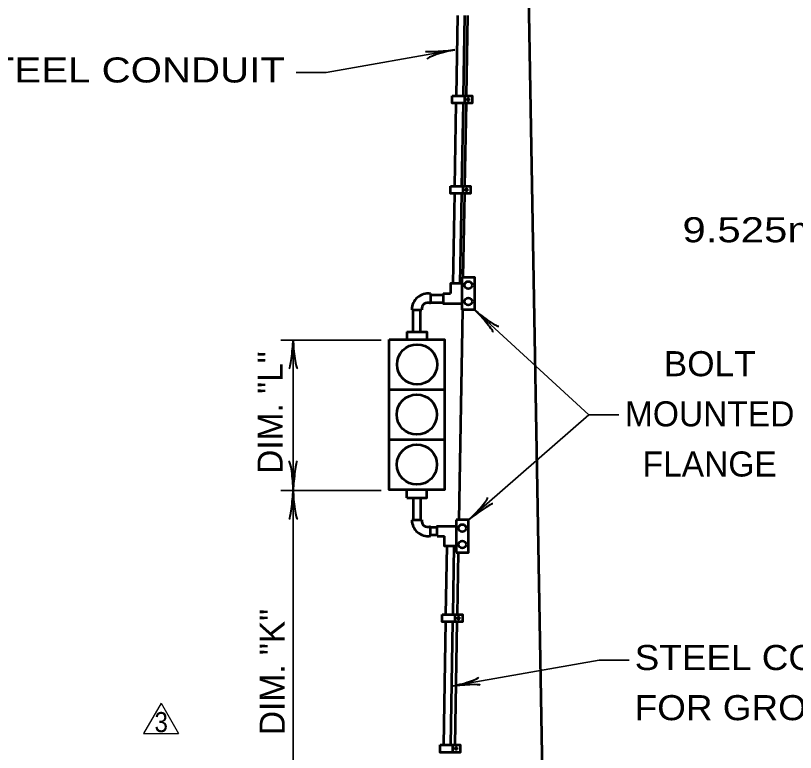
# Model space of a CAD drawing. Extents: x 14808 to 15663, y 10944 to 11488.
# Drawn here: x 15128.3 to 15221.6, y 11289.8 to 11377.9 of the extents above; entities that cross this region are included whole.
import ezdxf
from ezdxf.enums import TextEntityAlignment as Align

# ---------------------------------------------------------------- set-up
doc = ezdxf.new("R2010")
doc.units = 0
doc.header["$LTSCALE"] = 1.2
doc.layers.add('1', color=7, linetype='Continuous', lineweight=53)

msp = doc.modelspace()

# ---------------------------------------------------------------- linework, layer by layer
at = {"layer": '1'}
for p, q in [((15188.438, 11450.597), (15191.474, 11276.623)), ((15181.167, 11377.907), (15181, 11368.32)), ((15182.007, 11377.912), (15181.84, 11368.318)), ((15182.369, 11377.912), (15182.202, 11368.318)), ((15182.016, 11368.319), (15182.016, 11367.419)), ((15180.984, 11367.414), (15180.811, 11357.513)), ((15181.824, 11367.414), (15181.651, 11357.521)), ((15182.186, 11367.416), (15182.013, 11357.517)), ((15181.815, 11357.515), (15181.815, 11356.615)), ((15180.795, 11356.616), (15180.608, 11345.87)), ((15181.635, 11356.611), (15181.448, 11345.87)), ((15181.997, 11356.607), (15181.823, 11346.623)), ((15181.704, 11342.722), (15181.704, 11346.623)), ((15177.933, 11344.67), (15177.933, 11343.47)), ((15177.933, 11344.496), (15179.397, 11344.496)), ((15179.433, 11344.67), (15180.333, 11344.67)), ((15177.933, 11343.603), (15179.416, 11343.603)), ((15175.704, 11342.722), (15176.904, 11342.722)), ((15175.862, 11340.065), (15175.862, 11342.729)), ((15176.755, 11340.065), (15176.755, 11342.748)), ((15181.755, 11342.722), (15181.316, 11317.584)), ((15175.109, 11340.065), (15175.109, 11339.165)), ((15173.009, 11333.165), (15179.609, 11333.165)), ((15179.609, 11327.165), (15173.009, 11327.165)), ((15175.109, 11320.228), (15175.109, 11321.128)), ((15175.862, 11320.228), (15175.862, 11317.564)), ((15176.755, 11320.228), (15176.755, 11317.545)), ((15175.704, 11317.571), (15176.904, 11317.571)), ((15180.99, 11317.589), (15180.99, 11313.689)), ((15182.49, 11317.589), (15180.99, 11317.589)), ((15177.933, 11315.673), (15177.933, 11316.823)), ((15177.933, 11316.689), (15178.719, 11316.689)), ((15177.933, 11315.796), (15178.719, 11315.796)), ((15178.719, 11315.641), (15179.619, 11315.641)), ((15179.89, 11314.45), (15179.747, 11306.274)), ((15180.73, 11314.45), (15180.587, 11306.274)), ((15181.248, 11313.675), (15181.119, 11306.274)), ((15180.846, 11306.274), (15180.846, 11305.374)), ((15179.731, 11305.364), (15179.474, 11290.658)), ((15180.571, 11305.364), (15180.314, 11290.658)), ((15181.103, 11305.364), (15180.846, 11290.667)), ((15180.577, 11290.659), (15180.577, 11289.759))]:
    msp.add_line(p, q, dxfattribs=at)
at = {"layer": '1', "lineweight": 35}
for p, q in [((15183.204, 11342.722), (15196.87, 11330.165)), ((15172.04, 11339.093), (15160.04, 11339.093)), ((15172.04, 11321.093), (15160.04, 11321.093))]:
    msp.add_line(p, q, dxfattribs=at)
at = {"layer": '1', "lineweight": 25}
for p, q in [((15145.704, 11295.641), (15143.604, 11292.003)), ((15145.704, 11295.641), (15147.804, 11292.003)), ((15143.604, 11292.003), (15147.804, 11292.003))]:
    msp.add_line(p, q, dxfattribs=at)
at = {"layer": '1', "lineweight": 35}
for points in [[(15180.826, 11373.816), (15165.463, 11371.107), (15161.863, 11371.107)], [(15161.508, 11339.136), (15161.508, 11321.136), (15161.508, 11276.623)], [(15182.49, 11317.589), (15196.87, 11330.165), (15200.47, 11330.165)], [(15180.393, 11297.665), (15198.119, 11300.79), (15201.719, 11300.79)]]:
    msp.add_lwpolyline(points, dxfattribs=at)
at = {"layer": '1'}
for points in [[(15180.516, 11368.319), (15182.916, 11368.319), (15182.916, 11367.419), (15180.516, 11367.419)], [(15180.315, 11357.515), (15182.715, 11357.515), (15182.715, 11356.615), (15180.315, 11356.615)], [(15173.009, 11339.165), (15179.609, 11339.165), (15179.609, 11321.165), (15173.009, 11321.165)], [(15179.346, 11306.274), (15181.746, 11306.274), (15181.746, 11305.374), (15179.346, 11305.374)], [(15179.077, 11290.659), (15181.477, 11290.659), (15181.477, 11289.759), (15179.077, 11289.759)]]:
    msp.add_lwpolyline(points, close=True, dxfattribs=at)
for points in [[(15181.704, 11346.623), (15183.204, 11346.623), (15183.204, 11342.722)], [(15181.699, 11345.87), (15180.333, 11345.87), (15180.333, 11344.67)], [(15179.433, 11344.67), (15179.433, 11343.47), (15181.695, 11343.47)], [(15183.204, 11342.722), (15181.802, 11342.722), (15181.704, 11342.722)], [(15175.109, 11340.065), (15177.509, 11340.065), (15177.509, 11339.165)], [(15175.109, 11320.228), (15177.509, 11320.228), (15177.509, 11321.128)], [(15180.99, 11313.689), (15182.49, 11313.689), (15182.49, 11317.589)], [(15178.719, 11315.641), (15178.719, 11316.841), (15180.981, 11316.841)], [(15180.985, 11314.441), (15179.619, 11314.441), (15179.619, 11315.641)]]:
    msp.add_lwpolyline(points, dxfattribs=at)
for centre, radius in [((15182.453, 11367.873), 0.12), ((15182.252, 11357.069), 0.12), ((15182.457, 11345.674), 0.444), ((15182.457, 11343.711), 0.444), ((15176.334, 11336.172), 2.4), ((15176.298, 11330.183), 2.4), ((15176.307, 11324.194), 2.4), ((15181.743, 11316.601), 0.444), ((15181.743, 11314.637), 0.444), ((15181.282, 11305.828), 0.12), ((15181.013, 11290.213), 0.12)]:
    msp.add_circle(centre, radius, dxfattribs=at)
for centre, radius, start, end in [((15177.609, 11342.743), 1.905, 80.22862, 180.62498), ((15177.588, 11342.863), 0.698, 60.40406, 191.58246), ((15177.609, 11317.55), 1.905, 179.69885, 279.77138), ((15177.588, 11317.43), 0.698, 168.41754, 299.59594)]:
    msp.add_arc(centre, radius, start, end, dxfattribs=at)
at = {"layer": '1', "lineweight": 40}
for centre, major_axis, ratio, start_param, end_param in [((15179.458, 11373.832), (2.112, 0.158), 0.07063, 3.140715, 5.41811), ((15179.594, 11373.262), (2.078, 0.557), 0.122415, 0.896353, 3.141593), ((15184.022, 11341.626), (-1.409, 1.581), 0.07063, 3.140715, 5.41811), ((15184.393, 11342.081), (-1.705, 1.312), 0.122415, 0.896353, 3.141593), ((15161.254, 11337.791), (-0.211, -2.108), 0.07063, 6.282307, 8.559703), ((15161.84, 11337.826), (-0.187, 2.143), 0.122415, 0.896353, 3.141593), ((15161.177, 11322.445), (0.187, -2.143), 0.122415, 0.896353, 3.141593), ((15161.762, 11322.48), (0.211, 2.108), 0.07063, 6.282307, 8.559703), ((15161.254, 11319.791), (-0.211, -2.108), 0.07063, 6.282307, 8.559703), ((15161.84, 11319.826), (-0.187, 2.143), 0.122415, 0.896353, 3.141593), ((15183.258, 11318.7), (-1.49, -1.552), 0.122415, 0.896353, 3.141593), ((15183.669, 11318.283), (1.725, 1.229), 0.07063, 6.282307, 8.559703), ((15181.625, 11298.219), (-2.078, -0.557), 0.122415, 0.896353, 3.141593), ((15181.761, 11297.648), (2.112, 0.158), 0.07063, 6.282307, 8.559703)]:
    msp.add_ellipse(centre, major_axis=major_axis, ratio=ratio, start_param=start_param, end_param=end_param, dxfattribs=at)

# ---------------------------------------------------------------- texts
at = {"layer": '1'}
for s, width, p in [('31.8mm STEEL CONDUIT', 1.2, (15160.519, 11369.91)), ('9.525mmx63.5mm LAG SCREW', 1.25, (15281.087, 11350.792))]:
    msp.add_text(s, height=3, dxfattribs=dict(at, width=width)).set_placement(p, align=Align.RIGHT)
at = {"layer": '1', "width": 1.05}
msp.add_text('BOLT', height=3, dxfattribs=at).set_placement((15211.335, 11334.766), align=Align.CENTER)
at = {"layer": '1'}
for s, p in [('DIM. "L"', (15160.243, 11330.412)), ('DIM. "K"', (15160.498, 11299.375))]:
    msp.add_text(s, height=3, rotation=90, dxfattribs=at).set_placement(p, align=Align.CENTER)
for s, p in [('MOUNTED', (15211.335, 11328.766)), ('FLANGE', (15211.335, 11322.766))]:
    msp.add_text(s, height=3, dxfattribs=at).set_placement(p, align=Align.CENTER)
for s, height, width, p in [('STEEL CONDUIT', 3, 1.1, (15202.362, 11299.612)), ('FOR GROUND WIRE', 3, 1.1, (15202.362, 11293.612)), ('3', 2.4, 0.9, (15144.916, 11292.185))]:
    msp.add_text(s, height=height, dxfattribs=dict(at, width=width)).set_placement(p)

doc.saveas('drawing.dxf')
